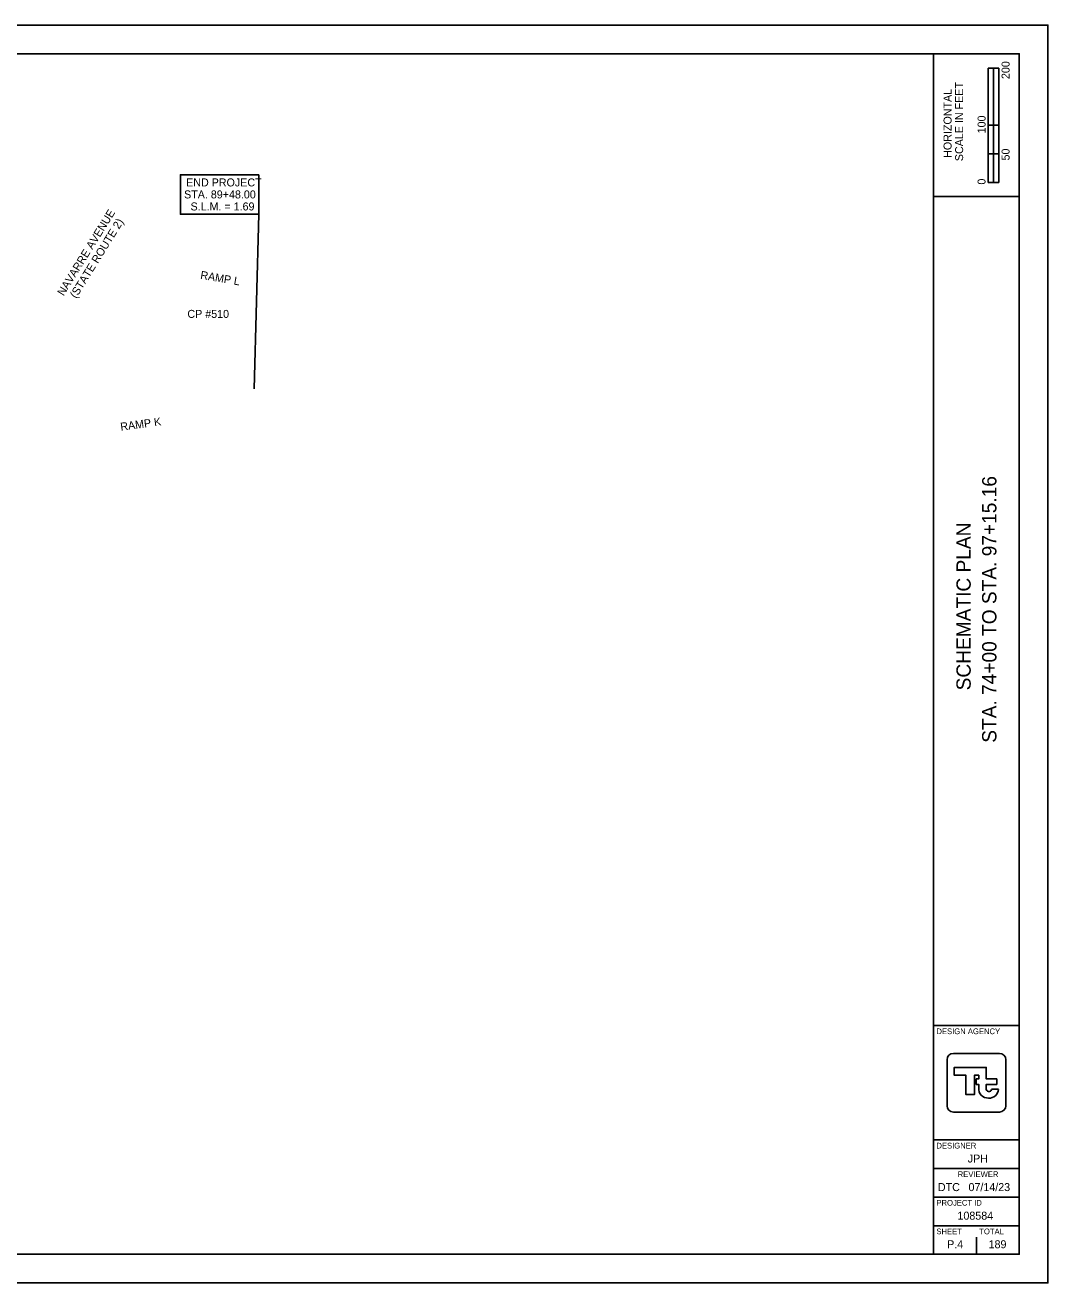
# Model space of a CAD drawing. Extents: x -1.8 to 34, y 0 to 22.
# Drawn here: x 16.1 to 34, y 0 to 22 of the extents above; entities that cross this region are included whole.
import ezdxf

# ---------------------------------------------------------------- set-up
doc = ezdxf.new("R2010")
doc.units = 0
for name, color, linetype in [('SH_Border', 7, 'Continuous'), ('SH_Cut_Line', 7, 'Continuous'), ('SH_Data', 7, 'Continuous'), ('SH_Text', 7, 'Continuous')]:
    doc.layers.add(name, color=color, linetype=linetype)

msp = doc.modelspace()

# ---------------------------------------------------------------- linework, layer by layer
at = {"layer": 'SH_Border'}
for p, q in [((32, 0.5), (32, 21.5)), ((32, 19), (33.5, 19)), ((32, 4.5), (33.5, 4.5)), ((32, 2.5), (33.5, 2.5)), ((32, 2), (33.5, 2)), ((32, 1.5), (33.5, 1.5)), ((32, 1), (33.5, 1))]:
    msp.add_line(p, q, dxfattribs=at)
msp.add_lwpolyline([(1.5, 21.5), (33.5, 21.5), (33.5, 0.5), (1.5, 0.5)], close=True, dxfattribs=at)
at = {"layer": 'SH_Cut_Line'}
msp.add_lwpolyline([(0, 0), (34, 0), (34, 22), (0, 22)], close=True, dxfattribs=at)
at = {"layer": 'SH_Data'}
for p, q in [((32.957, 19.25), (32.957, 21.25)), ((33.144, 21.25), (32.957, 21.25)), ((32.957, 20.25), (32.957, 21.25)), ((32.957, 21.25), (33.05, 21.25)), ((33.05, 21.25), (33.051, 21.25)), ((33.051, 21.25), (33.051, 20.25)), ((33.144, 21.25), (33.144, 19.25)), ((33.051, 20.25), (32.957, 20.25)), ((33.143, 20.25), (33.05, 20.25)), ((33.05, 20.25), (33.05, 19.75)), ((33.143, 19.75), (33.143, 20.25)), ((33.05, 19.75), (32.957, 19.75)), ((32.957, 19.75), (32.957, 19.25)), ((33.05, 19.25), (33.05, 19.75)), ((33.05, 19.75), (33.143, 19.75)), ((33.144, 19.25), (32.957, 19.25)), ((32.957, 19.25), (33.05, 19.25)), ((32.75, 3.5), (32.75, 3.5)), ((32.791, 3.415), (32.791, 3.415)), ((33.136, 3.385), (33.015, 3.385)), ((32.375, 0.675), (32.375, 0.675)), ((32.75, 0.5), (32.75, 0.8))]:
    msp.add_line(p, q, dxfattribs=at)
for points in [[(32.348, 4.014), (33.152, 4.014)], [(32.236, 3.099), (32.236, 3.901)], [(32.922, 3.399), (32.922, 3.47), (33.107, 3.47), (33.107, 3.568), (32.922, 3.568), (32.922, 3.768), (32.361, 3.768), (32.361, 3.632), (32.566, 3.632), (32.566, 3.294), (32.715, 3.294), (32.715, 3.63), (32.79, 3.63), (32.79, 3.568), (32.748, 3.568), (32.748, 3.47), (32.79, 3.47), (32.79, 3.415), (32.791, 3.415)], [(33.264, 3.901), (33.264, 3.099)], [(33.152, 2.986), (32.348, 2.986)]]:
    msp.add_lwpolyline(points, dxfattribs=at)
for centre, radius, start, end in [((32.348, 3.901), 0.113, 90, 180), ((33.152, 3.901), 0.113, 360, 90), ((32.949, 3.392), 0.16, 171.8856, 274.8323), ((32.968, 3.392), 0.0473, 171.8856, 350.9243), ((32.976, 3.392), 0.16, 265.1677, 357.3201), ((32.348, 3.099), 0.113, 180, 270), ((33.152, 3.099), 0.113, 270, 360)]:
    msp.add_arc(centre, radius, start, end, dxfattribs=at)
at = {"layer": 'SH_Text'}
msp.add_line((20.113, 15.636), (20.191, 18.691), dxfattribs=at)
msp.add_lwpolyline([(20.191, 19.383), (18.819, 19.383), (18.819, 18.691), (20.191, 18.691)], close=True, dxfattribs=at)

# ---------------------------------------------------------------- texts
at = {"layer": 'SH_Data'}
for s, height, p in [('200', 0.14, (33.33, 21.057)), ('SCALE IN FEET', 0.14, (32.517, 19.621)), ('HORIZONTAL', 0.14, (32.315, 19.679)), ('100', 0.14, (32.91, 20.107)), ('50', 0.14, (33.33, 19.633)), ('0', 0.14, (32.91, 19.211)), ('STA. 74+00 TO STA. 97+15.16', 0.25, (33.1, 9.448)), ('SCHEMATIC PLAN', 0.25, (32.65, 10.364))]:
    msp.add_text(s, height=height, rotation=90, dxfattribs=at).set_placement(p)
for s, height, p in [('DESIGN AGENCY', 0.1, (32.05, 4.35)), ('DESIGNER', 0.1, (32.05, 2.35)), ('JPH', 0.14, (32.598, 2.105)), ('REVIEWER', 0.1, (32.422, 1.85)), ('DTC', 0.14, (32.076, 1.605)), ('07/14/23', 0.14, (32.611, 1.605)), ('PROJECT ID', 0.1, (32.05, 1.35)), ('108584', 0.14, (32.418, 1.105)), ('SHEET', 0.1, (32.05, 0.85)), ('TOTAL', 0.1, (32.8, 0.85)), ('P.4', 0.14, (32.237, 0.605)), ('189', 0.14, (32.963, 0.605))]:
    msp.add_text(s, height=height, dxfattribs=at).set_placement(p)
at = {"layer": 'SH_Text'}
for s, p in [('END PROJECT', (18.92, 19.179)), ('STA. 89+48.00', (18.884, 18.969)), ('S.L.M. = 1.69', (18.997, 18.759)), ('CP #510', (18.942, 16.879))]:
    msp.add_text(s, height=0.14, dxfattribs=at).set_placement(p)
for s, rotation, p in [('NAVARRE AVENUE', 58.2455, (16.775, 17.254)), ('(STATE ROUTE 2)', 58.2455, (16.995, 17.21)), ('RAMP L', 350.2124, (19.161, 17.565)), ('RAMP K', 7.6725, (17.778, 14.904))]:
    msp.add_text(s, height=0.14, rotation=rotation, dxfattribs=at).set_placement(p)

doc.saveas('drawing.dxf')
